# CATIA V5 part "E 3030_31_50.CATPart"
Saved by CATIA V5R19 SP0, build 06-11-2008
Definition: E 3030_31_50
Nomenclature: E 3030_31_50
Description: PART--DESC
Material "Steel": density 7860 kg/m3, Young's modulus 2e+11 Pa, Poisson ratio 0.266, thermal expansion 1.17e-05 1/K
Bounding box of the stored display mesh (mm): x -29.283 to -11.615, y -25 to 25, z -31 to 0
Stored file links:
  G:\UTB\Kombinované\Bakalářská práce\Catia\FORMA\E 3030_31_50.CATPart
  D:\Aplikace\CATIA\Nová složka\win_b64\startup\materials\Catalog.CATMaterial
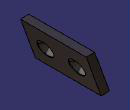
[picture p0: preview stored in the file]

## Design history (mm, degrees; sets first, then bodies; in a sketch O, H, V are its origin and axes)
Body1 "E 3030_31_50" (main body)
  Solid1: solid without history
